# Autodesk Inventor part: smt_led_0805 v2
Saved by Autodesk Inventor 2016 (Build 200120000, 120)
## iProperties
Created: 2016-09
Part Number: smt_led_0805 v2
Material: Generic
Document SubType Name: Modeling
Designer: Administrator
Appearance: Generic
Author: Administrator
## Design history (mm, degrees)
feature "Body1"
feature "Body2"
feature "Body3"
feature "Body4"
feature "Body5"
feature "Body6"
feature "Body8"
body "Solid1"
body "Solid2"
body "Solid3"
body "Solid4"
body "Solid5"
body "Solid6"
body "Solid7"
